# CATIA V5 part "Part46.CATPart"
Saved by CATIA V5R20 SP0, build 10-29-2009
Part number: FA 042200-3
Revision: ANY
Definition: UNKNOWN
Nomenclature: FA 042200-3
Source: Unknown
Bounding box of the stored display mesh (mm): x 0 to 2, y -1.45 to 1.45, z -1.45 to 1.45
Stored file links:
  C:\Users\Utente\Desktop\IO LAVORO\3D X SITO CF\CUMSA\3D files FA\FA 042204-20\Part46.CATPart

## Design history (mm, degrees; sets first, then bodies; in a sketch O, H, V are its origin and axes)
Body1 "Revolución1" (main body)
  Solid1: solid without history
